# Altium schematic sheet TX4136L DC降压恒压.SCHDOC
size B; SheetNumber: 0; SheetTotal: 0
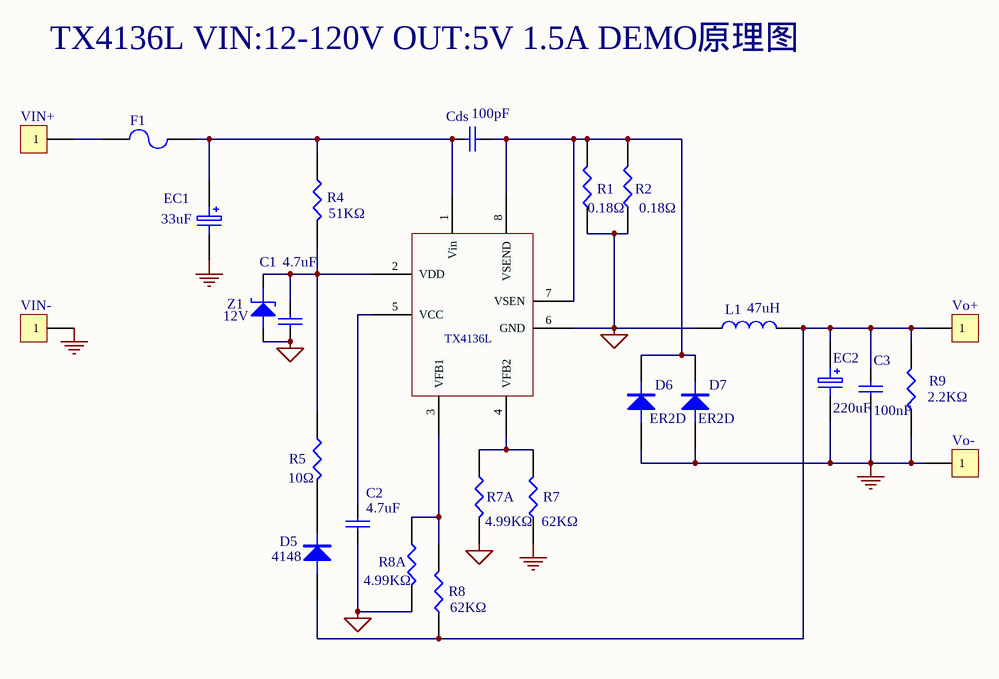
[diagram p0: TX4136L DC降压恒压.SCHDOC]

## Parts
?  TX4136L
C1  (no value)  [R0805]
C2  (no value)  [R1206]
C3  (no value)  [R1206]
Cds  (no value)
D5  (no value)
D6  (no value)  [SMB]
D7  (no value)  [SMB]
EC1  (no value)  [c10*16]
EC2  (no value)  [C10*16]
F1  (no value)
L1  (no value)  [L12*12]
R1  (no value)  [R1206]
R2  (no value)  [R1206]
R4  (no value)  [R1206]
R5  (no value)  [R1206]
R7  (no value)  [r0805]
R7A  (no value)  [r0805]
R8  (no value)  [r0805]
R8A  (no value)  [r0805]
R9  (no value)  [R0805]
VIN+  (no value)  [pad]
VIN-  (no value)
Vo+  (no value)  [pad]
Vo-  (no value)  [pad]
Z1  (no value)

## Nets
GND: C3.2 D6.1(A) D7.1(A) EC1.2 EC2.2 R7.1 R9.1 VIN-.1 Vo-.1
SGND: ?.6(GND) C1.2 C2.2 L1.1 R1.1 R2.1 R7A.2 R8A.2 Z1.1(A)
Net?_1: ?.1(Vin) Cds.1 EC1.1 F1.1 R4.1
Net?_2: ?.2(VDD) C1.1 R4.2 R5.1 Z1.2(K)
Net?_3: ?.3(VFB1) R8.2 R8A.1
Net?_4: ?.4(VFB2) R7.2 R7A.1
Net?_5: ?.5(VCC) C2.1
Net?_7: ?.7(VSEN) ?.8(VSEND) Cds.2 D6.2(K) D7.2(K) R1.2 R2.2
NetC3_1: C3.1 D5.1(A) EC2.1 L1.2 R8.1 R9.2 Vo+.1
NetD5_2: D5.2(K) R5.2
NetF1_2: F1.2 VIN+.1

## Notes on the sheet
- TX4136L VIN:12-120V OUT:5V 1.5A DEMO原理图
- (near Cds) 100pF
- (near EC1) 33uF
- (near R4) 51KΩ
- 0.18Ω
- (near R2) 0.18Ω
- 4.7uF
- (near Z1) 12V
- (near L1) 47uH
- (near D6) ER2D
- (near D7) ER2D
- 220uF
- (near R9) 100nF
- (near R9) 2.2KΩ
- (near R5) 10Ω
- (near D5) 4148
- (near C2) 4.7uF
- 4.99KΩ
- (near R7) 62KΩ
- (near R8A) 4.99KΩ
- (near R8) 62KΩ

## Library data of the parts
? = TX413XL
C1-C3 Cds = CAP: Capacitor
D5-D7 = DIODE
EC1 EC2 = ELECTRO1: Electrolytic Capacitor
F1 = FUSE2: Fuse
L1 = INDUCTOR
R1 R2 R4 R5 R7 R7A R8 R8A R9 = RES1
VIN+ VIN- Vo+ Vo- = CON1: Connector
Z1 = ZENER2: Zener Diode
